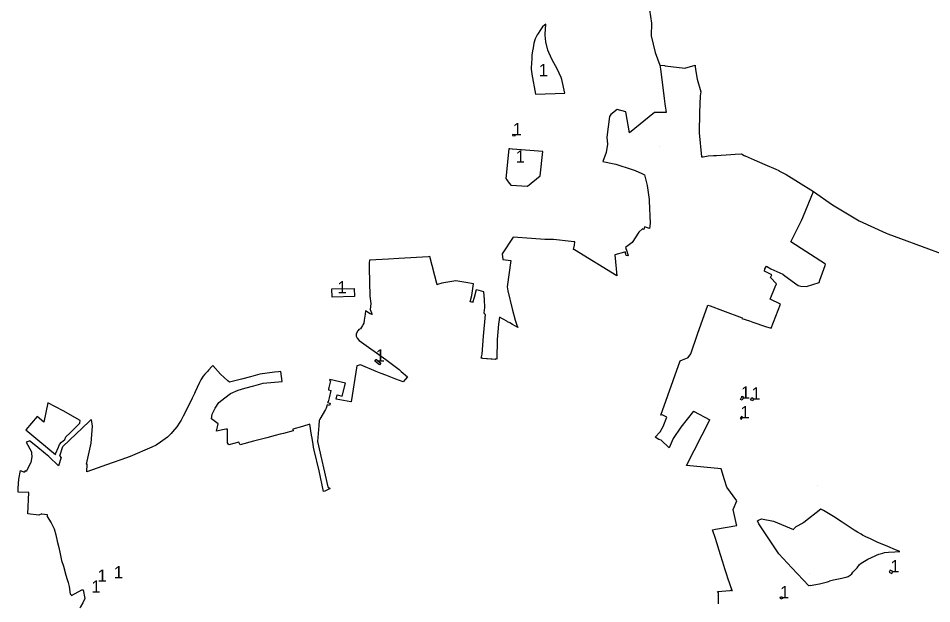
# Model space of a CAD drawing. Extents: x -798809 to -792931, y -1140324 to -1136346.
# Drawn here: x -796159 to -794302, y -1139073 to -1137884 of the extents above; entities that cross this region are included whole.
import ezdxf

# ---------------------------------------------------------------- set-up
doc = ezdxf.new("R2010")
doc.units = 0
for name, color, linetype in [('HRA_KU', 7, 'Continuous'), ('NERES_SET', 7, 'Continuous'), ('OVNE_PRE', 7, 'Continuous'), ('OVNE_SET', 7, 'Continuous'), ('OVNI_SET', 7, 'Continuous'), ('OZN', 7, 'Continuous')]:
    doc.layers.add(name, color=color, linetype=linetype)

msp = doc.modelspace()

# ---------------------------------------------------------------- linework, layer by layer
at = {"layer": 'HRA_KU'}
msp.add_lwpolyline([(-794854.9, -1137979), (-794845.5, -1137980.1), (-794844, -1137980.2), (-794804, -1137985.2), (-794783.5, -1137979.4), (-794783.1, -1137982), (-794782.3, -1137987.6), (-794779.2, -1138007.5), (-794771.9, -1138033.1), (-794772.9, -1138041.5), (-794774.3, -1138075.2), (-794774.9, -1138116.3), (-794770.2, -1138165.6), (-794767.1, -1138165.1), (-794759.9, -1138163.9), (-794756.9, -1138163.3), (-794746, -1138162.9), (-794739.8, -1138162.6), (-794739.8, -1138162.9), (-794710.6, -1138160.8), (-794702, -1138160.2), (-794689.3, -1138159.3), (-794688.8, -1138159.3), (-794683.6, -1138162.4), (-794682, -1138163.1), (-794681.5, -1138163.3), (-794663.4, -1138171.2), (-794641.4, -1138180.9), (-794619.3, -1138190.6), (-794613.4, -1138193.2), (-794613.2, -1138193.6), (-794609.3, -1138195.5), (-794601, -1138199.8), (-794598.3, -1138201.4), (-794572.9, -1138216.8), (-794542.8, -1138235.9)], dxfattribs=at)
at = {"layer": 'NERES_SET'}
for points in [[(-795073.7, -1137968), (-795080.5, -1137953.6), (-795082.7, -1137948.5), (-795086.6, -1137932), (-795087.7, -1137925.1), (-795088.1, -1137918), (-795088, -1137916.4), (-795086.4, -1137896.1), (-795088.8, -1137897), (-795093.3, -1137901.4), (-795099, -1137909.2), (-795102.4, -1137914.6), (-795104.1, -1137917.2), (-795108.1, -1137925.8), (-795110.8, -1137934.7), (-795112.7, -1137943.9), (-795113.8, -1137949.8), (-795115, -1137959), (-795115.3, -1137965.5), (-795116.3, -1137984.6), (-795116.5, -1137987.8), (-795116.1, -1137991), (-795115.4, -1137997.1), (-795107.4, -1138038.1), (-795048.1, -1138036), (-795054, -1138008.2), (-795055.6, -1138004.5), (-795063.5, -1137986.7)], [(-795161.7, -1138148.8), (-795168.3, -1138209.4), (-795166.2, -1138211.9), (-795163.2, -1138215.9), (-795157.8, -1138222.7), (-795123.9, -1138225.2), (-795098.3, -1138203.7), (-795092.9, -1138154.8), (-795154.7, -1138149.4), (-795155.3, -1138149.4), (-795159.6, -1138149)], [(-795521.4, -1138433.7), (-795476.3, -1138432.5), (-795475.9, -1138448.8), (-795520.9, -1138450)], [(-795430.7, -1138577.2), (-795422.1, -1138584.1), (-795425.1, -1138587.8), (-795434.3, -1138580.5), (-795431.3, -1138576.8)], [(-794688.1, -1138651.5), (-794685.2, -1138652.8), (-794685.5, -1138653.8), (-794684.8, -1138654.1), (-794687.5, -1138659.6), (-794691.1, -1138657.9), (-794688.5, -1138652.4)], [(-794668.1, -1138654.2), (-794663.8, -1138656.5), (-794666.2, -1138660.9), (-794670.5, -1138658.6)], [(-794689.3, -1138692.6), (-794691.4, -1138696.8), (-794689.1, -1138698), (-794687, -1138693.8)], [(-794386.9, -1139005), (-794388.7, -1139008.8), (-794383.2, -1139011.4), (-794381.3, -1139007.6)], [(-794610.6, -1139059.9), (-794606.9, -1139058.4), (-794605.4, -1139062.2), (-794609.1, -1139063.7)]]:
    msp.add_lwpolyline(points, close=True, dxfattribs=at)
for points in [[(-795154.4, -1138119.8), (-795154.6, -1138122)], [(-795154.6, -1138122), (-795149.2, -1138122.5)], [(-795149, -1138120.3), (-795154.4, -1138119.8)], [(-795149.2, -1138122.5), (-795149, -1138120.3)]]:
    msp.add_lwpolyline(points, dxfattribs=at)
at = {"layer": 'OVNE_PRE'}
for points in [[(-794876.2, -1137866.6), (-794871.8, -1137894.1), (-794872.5, -1137919.8), (-794864.3, -1137953.2), (-794854.9, -1137979)], [(-794542.8, -1138235.9), (-794503.8, -1138262.8), (-794449.7, -1138295.6), (-794394.7, -1138320.5), (-794391.3, -1138321.7), (-794365.9, -1138331.1), (-794277.9, -1138363.7)]]:
    msp.add_lwpolyline(points, dxfattribs=at)
at = {"layer": 'OVNE_SET'}
for p, q in [((-795149, -1138120.3), (-795149, -1138120.3)), ((-795149, -1138120.3), (-795149, -1138120.3)), ((-794855.2, -1138144.1), (-794855.2, -1138144.1)), ((-794855.2, -1138144.1), (-794855.2, -1138144.1)), ((-795103, -1138155.7), (-795103, -1138155.7)), ((-794533.8, -1138832.3), (-794533.8, -1138832.3))]:
    msp.add_line(p, q, dxfattribs=at)
at = {"layer": 'OVNI_SET'}
for p, q in [((-796076.8, -1138798.6), (-796076.8, -1138798.6)), ((-794533.8, -1138832.3), (-794533.8, -1138832.3)), ((-794550.7, -1139011.4), (-794550.7, -1139011.4))]:
    msp.add_line(p, q, dxfattribs=at)
for points in [[(-794854.9, -1137979), (-794853.6, -1137987.3), (-794849.5, -1138018.9), (-794845.9, -1138046.8), (-794844.5, -1138057.4), (-794843.9, -1138062.3), (-794842.7, -1138070.8), (-794842.2, -1138075), (-794842.2, -1138075.5), (-794866.1, -1138075.2), (-794916.7, -1138116.7), (-794924.1, -1138074), (-794941.6, -1138068.9), (-794954.7, -1138079.1), (-794957, -1138083.4), (-794962.6, -1138125.4), (-794961.4, -1138139.4), (-794964.4, -1138156.6), (-794970.6, -1138174.9), (-794947.5, -1138179.6), (-794944.3, -1138180.2), (-794911, -1138191.2), (-794905.1, -1138193.1), (-794891.5, -1138199.2), (-794886.1, -1138201.6), (-794884.7, -1138207.3), (-794880.8, -1138223.5), (-794876.9, -1138252), (-794876.5, -1138254.9), (-794874.9, -1138300.4), (-794876.2, -1138310.8), (-794886, -1138307.7), (-794887.6, -1138313.1), (-794890.4, -1138311.6), (-794897.7, -1138318), (-794911.1, -1138339.3), (-794924.5, -1138349.4), (-794922.2, -1138356.8), (-794919.5, -1138366.1), (-794923.5, -1138365.4), (-794924, -1138363.3), (-794925.2, -1138358.2), (-794926.7, -1138358.7), (-794946.7, -1138364.5), (-794942.7, -1138406.8), (-795028.2, -1138354.4), (-795030.6, -1138353.2), (-795028.1, -1138344.8), (-795027.6, -1138338.2), (-795028.6, -1138337.9), (-795029.6, -1138337.6), (-795035.5, -1138337), (-795070.8, -1138333.1), (-795089, -1138333.1), (-795115.5, -1138331.1), (-795153.1, -1138328.4), (-795175.6, -1138362.4), (-795174.3, -1138373.9), (-795158, -1138375.8), (-795165.6, -1138429.4), (-795163.6, -1138437.2), (-795154.8, -1138474), (-795149.2, -1138497.3)], [(-794786.5, -1138682.1), (-794812.5, -1138714.3), (-794828.1, -1138737.3), (-794835.9, -1138756), (-794852.6, -1138740.7), (-794856.8, -1138739.5), (-794864.8, -1138734.5), (-794854, -1138723.5), (-794848.2, -1138712.8), (-794840.8, -1138693.8), (-794850, -1138689.6), (-794852.8, -1138689.8), (-794813.8, -1138579.6), (-794808.8, -1138577.8), (-794799, -1138573.4), (-794797.7, -1138572.7), (-794792.1, -1138565.2), (-794778.2, -1138525.6), (-794757.5, -1138466.7), (-794757.1, -1138466.3), (-794752.8, -1138467.9), (-794727.3, -1138477.6), (-794687.9, -1138492.2), (-794688, -1138493.3), (-794672.8, -1138498.7), (-794666.2, -1138501), (-794639.9, -1138509.9), (-794628.7, -1138513.6), (-794610, -1138464.5), (-794630.6, -1138454.5), (-794620.3, -1138429.2), (-794617.9, -1138423.3), (-794629.8, -1138410.1), (-794627.8, -1138406), (-794627.3, -1138404.8), (-794642.4, -1138397.4), (-794641.3, -1138392.9), (-794637.9, -1138387.1), (-794629.2, -1138392.9), (-794605.2, -1138403.7), (-794601, -1138406.8), (-794573.9, -1138426.6), (-794568.6, -1138427.8), (-794557.1, -1138428.7), (-794531.3, -1138420.4), (-794529.6, -1138415.6), (-794519.2, -1138385.7), (-794518.3, -1138383.3), (-794588.6, -1138337.6), (-794567.3, -1138294.7), (-794564.1, -1138288.3), (-794563.2, -1138284.8), (-794542.8, -1138235.9)], [(-795240.6, -1138459.5), (-795237.3, -1138447.2), (-795233.6, -1138423.1), (-795249.4, -1138420.5), (-795269.3, -1138417.3), (-795298.2, -1138422.2), (-795306.7, -1138424.8), (-795307.9, -1138425.1), (-795322.5, -1138368), (-795325.5, -1138368.2), (-795385.6, -1138371.6), (-795406.8, -1138372.9), (-795445.2, -1138375.1), (-795445.5, -1138380.3), (-795445.9, -1138380.5), (-795446, -1138390.9), (-795444.4, -1138448.1), (-795442.1, -1138463), (-795443.6, -1138475.5), (-795439.4, -1138485.4), (-795443.9, -1138484.2), (-795453, -1138477.8), (-795454, -1138485.1), (-795455.8, -1138496.8), (-795456.6, -1138503), (-795458.6, -1138506.3), (-795459.5, -1138508), (-795463.3, -1138514.4), (-795466.8, -1138515.9), (-795468.2, -1138518.1), (-795468.7, -1138519), (-795472.2, -1138524.6), (-795472.4, -1138529.4), (-795470.5, -1138533.8), (-795466.4, -1138538.3), (-795411.6, -1138577.2), (-795384.9, -1138596.9), (-795380.6, -1138601.1), (-795367.6, -1138612.3), (-795376.8, -1138622.5), (-795391.6, -1138616.7), (-795401.7, -1138612.8), (-795411.8, -1138608.9), (-795421.3, -1138605.2), (-795431.6, -1138601.2), (-795463.4, -1138587.4), (-795470.8, -1138589.5), (-795482.5, -1138662.7), (-795482.8, -1138663.1), (-795512.7, -1138657.4), (-795510.7, -1138648.9), (-795500.5, -1138651.1), (-795494.2, -1138625), (-795525.6, -1138617.3), (-795526.1, -1138619.2), (-795524.2, -1138620), (-795527.5, -1138634), (-795528.2, -1138636.9), (-795528.6, -1138638.4), (-795523.4, -1138639.6), (-795526.9, -1138654.6), (-795528.8, -1138662.9), (-795529.9, -1138662.6), (-795530.3, -1138664.3), (-795525.1, -1138665.6), (-795526.3, -1138670.5), (-795531.4, -1138669.3), (-795532.5, -1138673.9), (-795533, -1138675.8), (-795534.2, -1138678.5), (-795546.2, -1138698.2), (-795547.5, -1138700.5), (-795548.3, -1138711), (-795550.9, -1138743.6), (-795530.1, -1138835.6), (-795525.4, -1138838.7), (-795524.9, -1138839.2), (-795535.8, -1138844.1), (-795538.5, -1138845.3), (-795547.7, -1138803.3), (-795557.4, -1138761.2), (-795558.6, -1138755.2), (-795559.6, -1138749), (-795560.2, -1138745.2), (-795561.7, -1138736.7), (-795562.7, -1138730.7), (-795566.5, -1138708.2), (-795581.2, -1138712.7), (-795600.7, -1138718.6), (-795600, -1138721.7), (-795619.8, -1138726.9), (-795626.9, -1138728.8), (-795636.7, -1138731.3), (-795654.1, -1138735.8), (-795667.2, -1138739.3), (-795681.2, -1138743), (-795708.3, -1138750.2), (-795710.8, -1138744.6), (-795730.7, -1138749.9), (-795733.8, -1138745.9), (-795733.6, -1138718.1), (-795736.5, -1138718.7), (-795740.7, -1138719.2), (-795756.1, -1138722.4), (-795752.8, -1138707.5), (-795766.2, -1138697.1), (-795765.1, -1138688.2), (-795758.5, -1138675.9), (-795751.5, -1138664.1), (-795739.4, -1138654.9), (-795727.3, -1138645.9), (-795711.9, -1138639.1), (-795698.3, -1138635.4), (-795680.4, -1138630.4), (-795661, -1138624.9), (-795622.6, -1138621.7), (-795625.2, -1138601.5), (-795630, -1138601.9), (-795638.5, -1138602.9), (-795668.1, -1138607), (-795686.8, -1138611.9), (-795705.4, -1138616.6), (-795729.7, -1138623.1), (-795733.2, -1138620.1), (-795748.2, -1138606.8), (-795763.2, -1138588.8), (-795765.3, -1138591.4), (-795765.6, -1138591.4), (-795772.4, -1138598.7), (-795774, -1138600.4), (-795779.8, -1138606.9), (-795783.5, -1138611), (-795787.7, -1138618.3), (-795790.8, -1138623.8), (-795795.3, -1138633.8), (-795799.2, -1138642.5), (-795800.9, -1138646.1), (-795805.5, -1138655.6), (-795818.1, -1138681.5), (-795823.7, -1138692.1), (-795828.2, -1138700.4), (-795830.7, -1138704.2), (-795836.9, -1138713.4), (-795845.4, -1138723.6), (-795848.3, -1138727.1), (-795852.9, -1138731.7), (-795855.6, -1138734.5), (-795869.7, -1138744.7), (-795878.6, -1138751.2), (-795887.4, -1138755), (-795931.6, -1138774.2), (-795950.4, -1138780.8), (-795966.4, -1138786.4), (-795968.2, -1138787)], [(-795143.7, -1138512), (-795146.9, -1138510.2), (-795149.8, -1138508.6), (-795154.2, -1138506.1), (-795160, -1138502.7), (-795164.5, -1138500.2), (-795166.3, -1138499.2), (-795181, -1138490.8), (-795183, -1138505.1), (-795185.3, -1138536.5), (-795186.3, -1138576.1), (-795188, -1138575.8), (-795189.3, -1138576), (-795189.4, -1138576.7), (-795195.6, -1138576.2), (-795198.2, -1138576), (-795198.8, -1138576), (-795205.5, -1138575.4), (-795206.1, -1138575.4), (-795207.1, -1138575.3), (-795215.4, -1138574.7), (-795215.4, -1138574), (-795218.1, -1138574.1), (-795216.2, -1138565.9), (-795213.6, -1138529.2), (-795209, -1138485.8), (-795210.6, -1138485.6), (-795212.2, -1138482.2), (-795211, -1138471), (-795211.5, -1138455.3), (-795213, -1138439.8), (-795222.3, -1138437.1), (-795228.5, -1138435.4), (-795232.2, -1138451.1), (-795235.5, -1138461.6)], [(-795235.5, -1138461.6), (-795236.6, -1138460.7), (-795240.6, -1138459.5)], [(-795149.2, -1138497.3), (-795145.5, -1138507.1), (-795143.7, -1138512)], [(-794786.5, -1138682.1), (-794753.1, -1138699.5)], [(-796073.2, -1138774), (-796074.4, -1138772.4), (-796068.2, -1138753.3), (-796014.6, -1138702.7), (-796014.1, -1138702.2), (-796010.5, -1138698.9), (-796009.1, -1138712.4), (-796011.2, -1138747), (-796021.2, -1138789.6)], [(-794735.7, -1139073.4), (-794735.8, -1139054.9), (-794735.9, -1139050.7), (-794737.8, -1139047.9), (-794712, -1139046.1), (-794711.6, -1139045.2), (-794711.5, -1139045.3), (-794708, -1139046.6), (-794708.2, -1139046.2), (-794717, -1139020.8), (-794718.9, -1139014.2), (-794720.8, -1139007.8), (-794722.8, -1139001.7), (-794727, -1138988.6), (-794731.7, -1138973.8), (-794741.8, -1138940.5), (-794747.6, -1138922.7), (-794742, -1138921.7), (-794698.5, -1138914.1), (-794699, -1138911.9), (-794706.1, -1138881.2), (-794698.5, -1138863.6), (-794718.7, -1138836.2), (-794723.5, -1138821.2), (-794730.6, -1138799), (-794801.1, -1138792), (-794753.1, -1138699.5)], [(-796077.4, -1138792.6), (-796096.6, -1138774), (-796103.5, -1138768.4), (-796123.4, -1138752.3), (-796136, -1138742.3), (-796136.8, -1138742.6), (-796143, -1138744.8), (-796132.2, -1138764.3), (-796132.1, -1138767), (-796131.7, -1138774.3), (-796133.3, -1138786), (-796143.1, -1138804.1), (-796145.3, -1138803)], [(-796071.9, -1138775.7), (-796077.4, -1138792.6)], [(-796071.9, -1138775.7), (-796073.2, -1138774)], [(-796111.2, -1138890.3), (-796117.4, -1138893.1), (-796139.8, -1138890.6), (-796137.7, -1138847.2), (-796159, -1138846.3), (-796159, -1138838.4), (-796157.6, -1138819.8), (-796154.6, -1138802.4)], [(-796154.6, -1138802.4), (-796147.1, -1138805.9)], [(-795968.2, -1138787), (-796019.8, -1138805.2), (-796019.3, -1138789.6), (-796021.2, -1138789.6)], [(-796145.3, -1138803), (-796147.1, -1138805.9)], [(-796111.2, -1138890.3), (-796100.6, -1138892)], [(-796100.6, -1138892), (-796100.5, -1138892.7), (-796100, -1138895.8), (-796092, -1138908.7), (-796086, -1138920.5), (-796082.8, -1138933.2), (-796079.8, -1138945.9), (-796076.6, -1138958.9), (-796073.6, -1138971.7), (-796070.8, -1138984.8), (-796067.2, -1138996.5), (-796062.1, -1139014.9), (-796059.7, -1139023.4), (-796057.9, -1139029.9), (-796055.7, -1139037.7), (-796053.3, -1139053.8)], [(-794502, -1138895.7), (-794522, -1138883.8), (-794527.5, -1138880.6), (-794562.2, -1138908.2), (-794564.1, -1138909.2), (-794578.7, -1138917), (-794582.3, -1138921)], [(-794549.1, -1139036.2), (-794551.9, -1139036.8), (-794586.9, -1138999.7), (-794613.3, -1138971.7), (-794653.7, -1138910.7), (-794656.8, -1138904.4), (-794654.2, -1138903.1), (-794648.1, -1138900.3), (-794624.2, -1138905.3), (-794583.4, -1138922.2), (-794582.3, -1138921)], [(-794472.2, -1139017.4), (-794468.3, -1139014.8), (-794464.7, -1139012.4), (-794462.4, -1139009), (-794454.2, -1139000.2), (-794449.3, -1138993.4), (-794446, -1138990.4), (-794442.7, -1138988.3), (-794439.1, -1138986.2), (-794431.9, -1138982.5), (-794417.2, -1138975.7), (-794414.4, -1138974.4), (-794409.7, -1138972.3), (-794401.9, -1138970), (-794398, -1138969.2), (-794389.9, -1138967.9), (-794377.1, -1138967.5), (-794367.3, -1138966.9), (-794375.9, -1138963.5), (-794391.7, -1138956.8), (-794413.3, -1138947.6), (-794414.7, -1138947), (-794421.3, -1138944), (-794427, -1138941.3), (-794436.5, -1138937.2), (-794442.9, -1138933.6), (-794446, -1138931.8), (-794452.9, -1138927.8), (-794460.1, -1138923.5), (-794465.9, -1138919.6), (-794484.2, -1138907.5), (-794502, -1138895.7)], [(-794472.2, -1139017.4), (-794473.2, -1139018.1), (-794477.2, -1139019.7), (-794484.8, -1139021.9), (-794502.1, -1139025.1), (-794510, -1139027.2)], [(-794549.1, -1139036.2), (-794530.3, -1139032.3), (-794519.5, -1139030.1), (-794514.1, -1139028.3), (-794510, -1139027.2)], [(-796053.3, -1139053.8), (-796051.9, -1139053.2)], [(-796051.9, -1139053.2), (-796050.8, -1139056.1), (-796029.8, -1139044.9), (-796027.2, -1139044.5), (-796023.6, -1139062.2), (-796028.1, -1139071.3), (-796032.2, -1139079.5), (-796033.8, -1139082.1)]]:
    msp.add_lwpolyline(points, dxfattribs=at)
msp.add_lwpolyline([(-796083.3, -1138769.7), (-796083.2, -1138769.4), (-796082.8, -1138768.7), (-796083, -1138768.4), (-796077.3, -1138755), (-796075, -1138749.2), (-796070.9, -1138744.7), (-796064.4, -1138739.2), (-796062.1, -1138734.1), (-796054.5, -1138726.6), (-796033.6, -1138706.1), (-796033.3, -1138701), (-796068, -1138681.4), (-796098.7, -1138664.8), (-796107, -1138704.1), (-796120.8, -1138692.6), (-796143.3, -1138719.6), (-796118.9, -1138739.9), (-796115.2, -1138743.6), (-796103.6, -1138753), (-796099.2, -1138756.9)], close=True, dxfattribs=at)

# ---------------------------------------------------------------- texts
at = {"layer": 'OZN'}
for p in [(-795100.8, -1138001.5), (-795154, -1138121.6), (-795147.7, -1138177.2), (-795510.1, -1138442.8), (-795432.6, -1138581.2), (-794690, -1138656.5), (-794668.9, -1138658.4), (-794690.9, -1138696.2), (-794386.4, -1139009.4), (-795997.8, -1139028.4), (-795964.6, -1139021.5), (-796010.3, -1139050.7), (-794610.5, -1139061.9)]:
    msp.add_text('1', height=25, dxfattribs=at).set_placement(p)

doc.saveas('drawing.dxf')
